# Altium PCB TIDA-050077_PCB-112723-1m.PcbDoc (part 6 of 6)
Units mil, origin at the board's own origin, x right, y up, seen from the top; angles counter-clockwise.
Board outline 3780 x 7750 mil, 16 copper layers (Top Layer, L2-Powet 1, L3-Power 2, L4-Power 3, L5-Power 4, L6-INT 1, L7-INT 2, L8-INT 3, L9-INT 4, L10-INT 5, L11-INT 6, L12-Power 5, L13-Power 6, L14-Power 7, L15-Power 8, Bottom Layer), stack 121.442 mil thick; 381 components, 136 nets, 958 pads, 3470 vias.
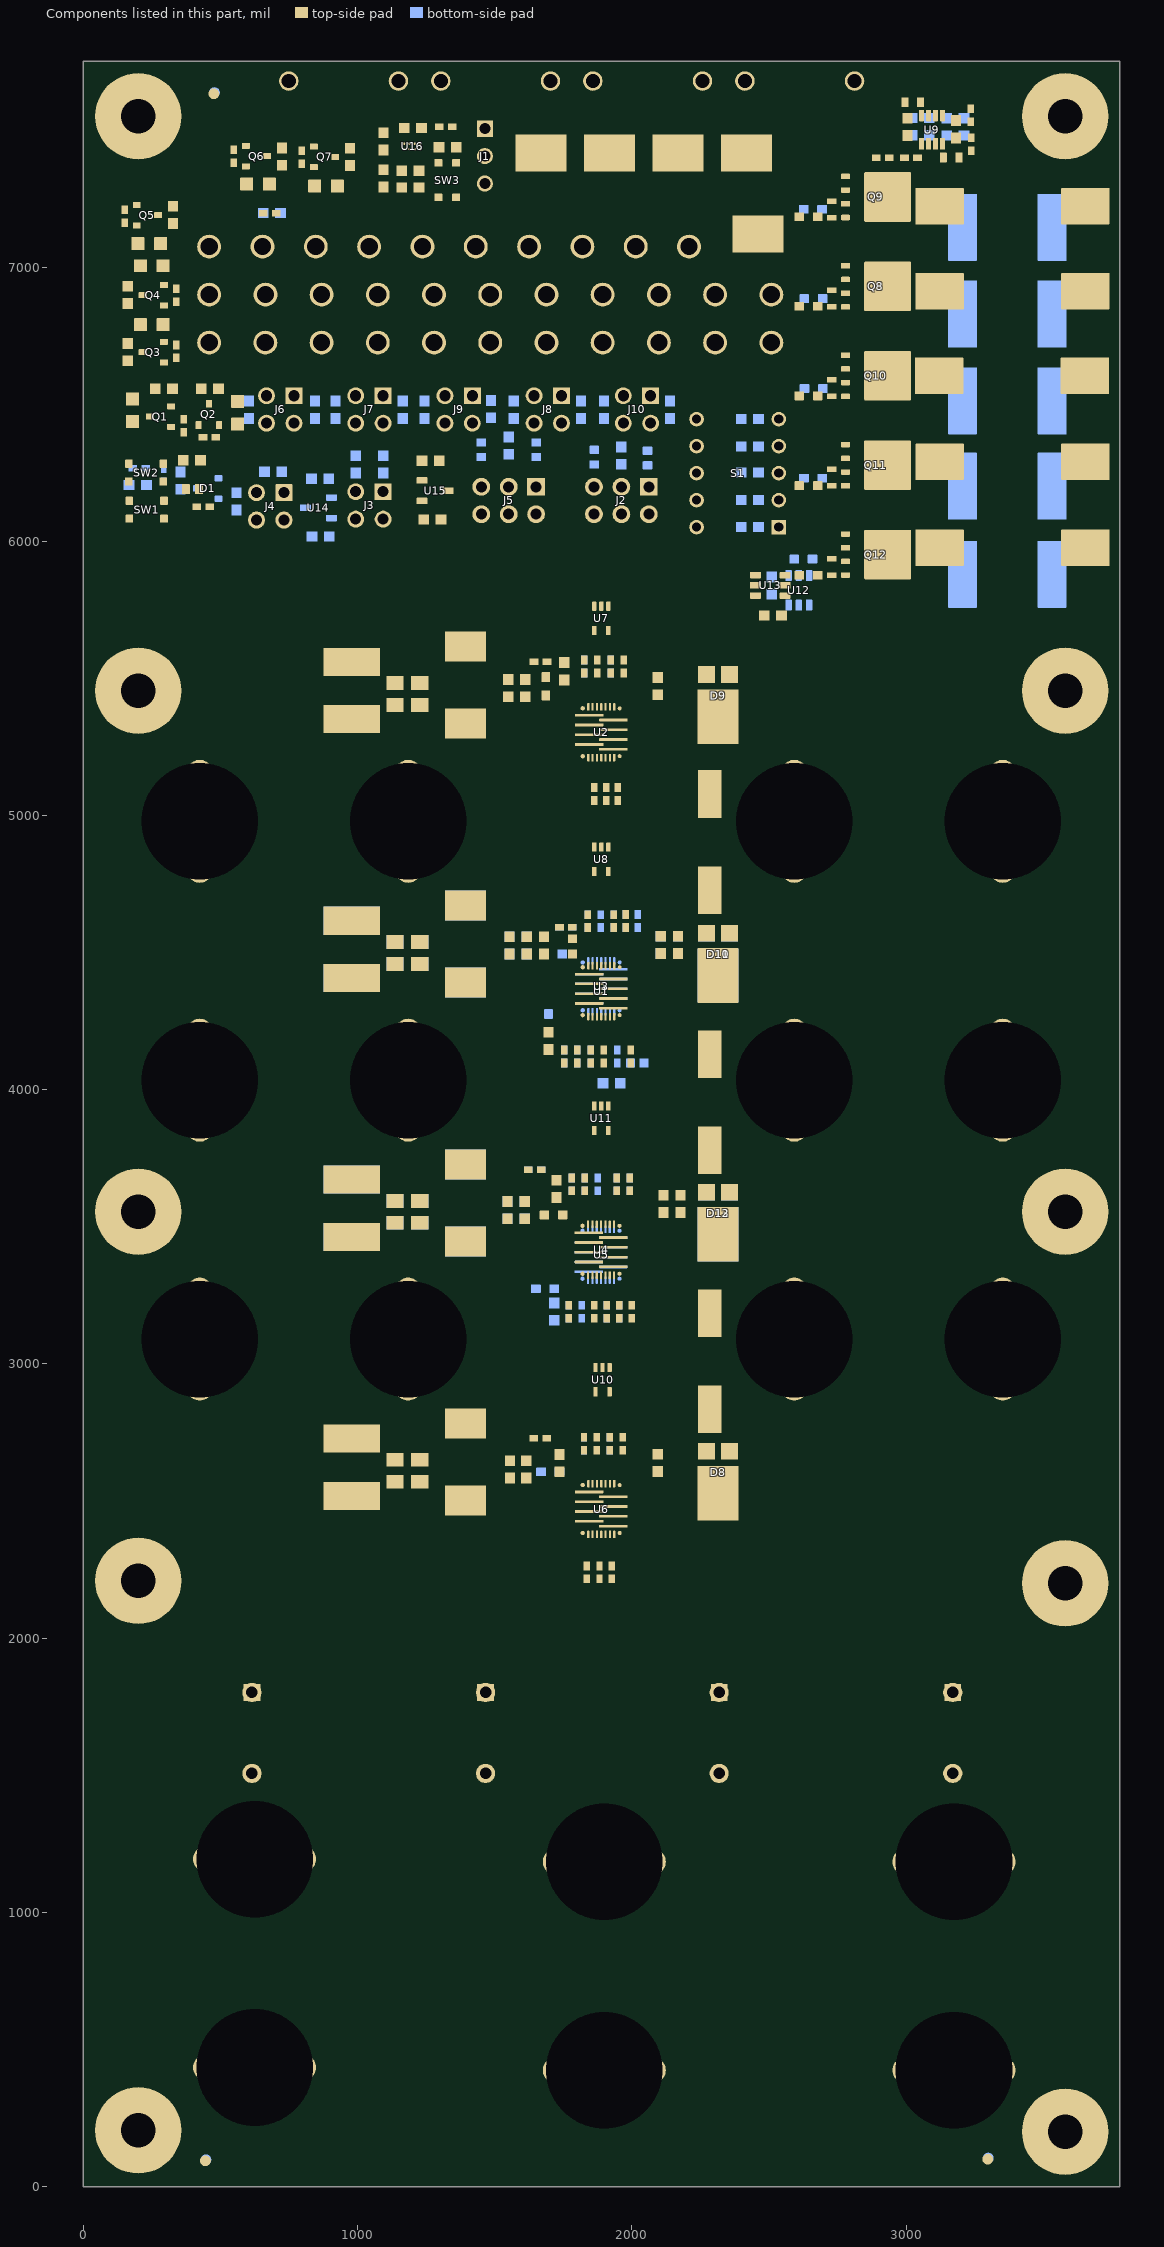
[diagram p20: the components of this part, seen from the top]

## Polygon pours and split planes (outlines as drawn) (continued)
VOUT on L15-Power 8 "L8_BOT_[PWR]_NONET_P-001" (solid, remove dead copper, pour order 1807): 3407.49,5212.29 3407.49,4755.86 3372.2,4720.57 2581.76,4720.57 2539.6,4762.73 2539.6,5216.49 2570.4,5247.29 3372.49,5247.29
VOUT on L15-Power 8 "L8_BOT_[PWR]_NONET_P-001" (solid, remove dead copper, pour order 1806): 3407.49,4268.09 3407.49,3811.67 3372.2,3776.37 2581.76,3776.37 2539.6,3818.53 2539.6,4272.29 2570.4,4303.09 3372.49,4303.09
VIN on L15-Power 8 "L8_BOT_[PWR]_NONET_P-001" (solid, remove dead copper, pour order 1682): 369.28,3804.7 369.28,4261.13 404.58,4296.42 1195.02,4296.42 1237.18,4254.26 1237.18,3800.51 1206.37,3769.7 404.28,3769.7
VIN on L15-Power 8 "L8_BOT_[PWR]_NONET_P-001" (solid, remove dead copper, pour order 1681): 369.28,4748.9 369.28,5195.87 414.03,5240.62 1195.02,5240.62 1237.18,5198.46 1237.18,4744.7 1206.37,4713.9 404.28,4713.9
QGND on L4-Power 3 "L4-POWER_3_QGND_P1609" (solid, remove dead copper, pour order 1609): 3352.36,7413.9 3386.33,7447.87 3386.33,7711.85 3373.67,7724.51 226.93,7724.51 29.23,7526.81 29.23,6081.96 82.37,6031.04 2585.13,6031.04 2654.12,6100.03 2654.12,7391.34 2676.68,7413.9
PGND on L4-Power 3 "L4-POWER_3_PGND_P1608" (solid, remove dead copper, pour order 1608): 26.96,56.7 55.66,28 3703.56,28 3746.15,70.6 3746.15,1660.54 3715.79,1690.9 48.73,1690.9 26.96,1669.12
VIN on L4-Power 3 "L4-POWER_3_VIN_P1819" (solid, remove dead copper, pour order 1819): 76.04,1723.9 1835.41,1723.9 1873.32,1761.8 1873.32,5995.34 1850.52,6018.73 73.45,6018.73 28.38,5973.66 28.38,1771.56
VOUT on L4-Power 3 "L4-POWER_3_VOUT_P1818" (solid, remove dead copper, pour order 1818): 1931.67,6018 2533.6,6018 2737.97,5813.63 3701.12,5813.63 3753.65,5761.09 3753.65,1751.37 3726.18,1723.9 1941.76,1723.9 1904.28,1761.37 1904.28,5990.62
VOUT on L4-Power 3 "L4-POWER_3_VOUT_P1603" (solid, remove dead copper, pour order 1603): 3380.94,7387.36 3721.81,7387.36 3744.28,7364.89 3744.28,5854.53 3713.49,5823.73 3391.9,5823.73 3359.28,5856.35 3359.28,7365.7
PGND on L4-Power 3 "L4-POWER_3_PGND_P1605" (solid, remove dead copper, pour order 1605): 2843.98,5931.08 2823.92,5911.02 2681.1,5911.02 2669.47,5922.65 2669.47,7376.14 2688.81,7395.49 2821.74,7395.49 2843.98,7373.25
CSA_IN- on L4-Power 3 "L4-POWER_3_CSA_IN-_P1604" (solid, remove dead copper, pour order 1604): 3332.59,5884.82 3304.22,5856.44 2882.86,5856.44 2858.8,5880.5 2858.8,7380.82 2873.03,7395.05 3312.43,7395.05 3332.59,7374.88

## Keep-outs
Keep-Out Layer:
  text ".Layer_Name" at -1006.87,-4296.96 h60

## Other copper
Top Layer:
  pour cut-out: 402.65,51.75 cw(c445.07,94.18) 402.65,136.61 cw(c445.07,94.18) 487.5,136.61 cw(c445.07,94.18) 487.5,51.75 cw(c445.07,94.18)
  pour cut-out: 3255.41,57.67 cw(c3297.84,100.1) 3255.41,142.52 cw(c3297.84,100.1) 3340.26,142.52 cw(c3297.84,100.1) 3340.26,57.67 cw(c3297.84,100.1)
  pour cut-out: 433.48,7589.49 cw(c475.9,7631.92) 433.48,7674.34 cw(c475.9,7631.92) 518.33,7674.34 cw(c475.9,7631.92) 518.33,7589.49 cw(c475.9,7631.92)
  region net VIN: 1766.64,3365.45 1786.59,3345.5 1867.13,3345.5 1869.84,3348.21 1869.84,3476.75 1864.12,3482.46 1772.57,3482.46 1766.64,3476.54
  region net VDD: 1770.34,4517.61 1765.34,4512.61 1765.34,4466.83 1794.15,4438.02 1828.21,4438.02 1829.58,4439.39 1829.58,4494.8 1806.77,4517.61
  region net VOUT: 1912.58,3347.33 2000.86,3347.33 2010.88,3357.35 2010.88,3473.97 1999.15,3485.71 1912.93,3485.71 1907.68,3480.46 1907.68,3458.33 1907.68,3352.23
  region net VOUT: 1912.58,2403.13 2000.86,2403.13 2010.88,2413.15 2010.88,2529.77 1999.15,2541.51 1912.93,2541.51 1907.68,2536.27 1907.68,2514.13 1907.68,2408.03
  region net VIN: 1766.64,2407.34 1773.87,2400.1 1865.94,2400.1 1869.84,2404 1869.84,2532.55 1864.12,2538.27 1771.32,2538.27 1766.64,2533.59
  region net VOUT: 1912.58,5235.72 2000.86,5235.72 2010.88,5245.74 2010.88,5362.36 1999.15,5374.1 1912.93,5374.1 1907.68,5368.85 1907.68,5346.72 1907.68,5240.62
  region net VIN: 1869.84,5365.14 1869.84,5235.75 1865.44,5231.34 1771.42,5231.34 1766.64,5236.12 1766.64,5366.8 1770.7,5370.86 1864.12,5370.86
  region net VOUT: 1912.58,4291.52 2000.86,4291.52 2010.88,4301.54 2010.88,4418.17 1999.15,4429.9 1912.93,4429.9 1907.68,4424.66 1907.68,4402.52 1907.68,4296.42
  region net VIN: 1793.92,4426.66 1864.12,4426.66 1869.84,4420.94 1869.84,4314.84 1864.94,4309.94 1791.44,4309.94 1787.04,4305.54 1770.74,4305.54 1766.64,4309.64 1766.64,4428.64 1771.14,4433.14 1787.44,4433.14
  text ".Layer_Name" at -1006.87,-4296.96 h60
L4-Power 3:
  text ".Layer_Name" at -1006.87,-4296.96 h60
L2-Powet 1:
  text ".Layer_Name" at -1006.87,-4296.96 h60
L8-INT 3:
  text ".Layer_Name" at -1006.87,-4296.96 h60
L3-Power 2:
  text ".Layer_Name" at -1006.87,-4296.96 h60
L7-INT 2:
  text ".Layer_Name" at -1006.87,-4296.96 h60
L5-Power 4:
  pour cut-out: 1332.85,5051.6 ccw(c1352.85,5051.6) 1352.85,5031.6 ccw(c1352.85,5051.6) 1372.85,5051.6 ccw(c1352.85,5051.6) 1352.85,5071.6 ccw(c1352.85,5051.6)
  text ".Layer_Name" at -1006.87,-4296.96 h60
L6-INT 1:
  text ".Layer_Name" at -1006.87,-4296.96 h60
L9-INT 4:
  text ".Layer_Name" at -1006.87,-4296.96 h60
L10-INT 5:
  text ".Layer_Name" at -1006.87,-4296.96 h60
L11-INT 6:
  text ".Layer_Name" at -1006.87,-4296.96 h60
L12-Power 5:
  text ".Layer_Name" at -1006.87,-4296.96 h60
L13-Power 6:
  text ".Layer_Name" at -1006.87,-4296.96 h60
L14-Power 7:
  text ".Layer_Name" at -1006.87,-4296.96 h60
L15-Power 8:
  text ".Layer_Name" at -1006.87,-4296.96 h60
Bottom Layer:
  pour cut-out: 404.75,55.83 cw(c447.18,98.26) 404.75,140.69 cw(c447.18,98.26) 489.61,140.69 cw(c447.18,98.26) 489.61,55.83 cw(c447.18,98.26)
  pour cut-out: 3257.52,61.75 cw(c3299.94,104.18) 3257.52,146.6 cw(c3299.94,104.18) 3342.37,146.6 cw(c3299.94,104.18) 3342.37,61.75 cw(c3299.94,104.18)
  pour cut-out: 435.58,7593.57 cw(c478.01,7636) 435.58,7678.42 cw(c478.01,7636) 520.43,7678.42 cw(c478.01,7636) 520.43,7593.57 cw(c478.01,7636)
  pour cut-out: 2649.62,7231.3 2668.59,7231.3 2668.59,7235.69 2649.62,7235.69
  text ".Layer_Name" at -1006.87,-4296.96 h60
Multi-Layer:
  pour cut-out: 20.22,7550 ccw(c200,7550) 200,7370.22 ccw(c200,7550) 379.78,7550 ccw(c200,7550) 200,7729.78 ccw(c200,7550)
  pour cut-out: 3400.22,7550 ccw(c3580,7550) 3580,7370.22 ccw(c3580,7550) 3759.78,7550 ccw(c3580,7550) 3580,7729.78 ccw(c3580,7550)
  pour cut-out: 3400.22,5455 ccw(c3580,5455) 3580,5275.22 ccw(c3580,5455) 3759.78,5455 ccw(c3580,5455) 3580,5634.78 ccw(c3580,5455)
  pour cut-out: 20.22,5455 ccw(c200,5455) 200,5275.22 ccw(c200,5455) 379.78,5455 ccw(c200,5455) 200,5634.78 ccw(c200,5455)
  pour cut-out: 20.22,3555 ccw(c200,3555) 200,3375.22 ccw(c200,3555) 379.78,3555 ccw(c200,3555) 200,3734.78 ccw(c200,3555)
  pour cut-out: 3400.22,3555 ccw(c3580,3555) 3580,3375.22 ccw(c3580,3555) 3759.78,3555 ccw(c3580,3555) 3580,3734.78 ccw(c3580,3555)
  pour cut-out: 3400.22,2200 ccw(c3580,2200) 3580,2020.22 ccw(c3580,2200) 3759.78,2200 ccw(c3580,2200) 3580,2379.78 ccw(c3580,2200)
  pour cut-out: 20.22,2208.9 ccw(c200,2208.9) 200,2029.12 ccw(c200,2208.9) 379.78,2208.9 ccw(c200,2208.9) 200,2388.68 ccw(c200,2208.9)
  pour cut-out: 20.22,205 ccw(c200,205) 200,25.22 ccw(c200,205) 379.78,205 ccw(c200,205) 200,384.78 ccw(c200,205)
  pour cut-out: 3400.22,200 ccw(c3580,200) 3580,20.22 ccw(c3580,200) 3759.78,200 ccw(c3580,200) 3580,379.78 ccw(c3580,200)

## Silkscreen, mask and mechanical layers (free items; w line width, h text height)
Top Overlay:
  lines w5: 24.28,6786.58 34.28,6786.58 ; 34.28,7085.12 34.28,7077.96 ; 35.1,7004.76 45.1,7004.76 ; 39.34,7083.01 34.28,7077.96 ; 41.44,7077.96 34.28,7077.96 ; 44.28,6776.58 44.28,6796.58 ; 45.1,7087.27 55.1,7087.27 ; 45.52,6806.41 52.68,6806.41 ; 46.7,7074.6 46.7,7067.44 ; 47.63,6801.35 52.68,6806.41 ; 51.75,7072.5 46.7,7067.44 ; 52.68,6799.25 52.68,6806.41 ; 53.86,7067.44 46.7,7067.44 ; 54.28,6786.58 44.28,6786.58 ; 55.1,6994.76 55.1,7014.76 ; 55.1,7077.27 55.1,7097.27 ; 56.34,7024.59 63.5,7024.59 ; 57.94,6795.89 65.1,6795.89 ; 58.44,7019.54 63.5,7024.59 ; 60.04,6790.84 65.1,6795.89 ; 63.5,7017.43 63.5,7024.59 ; 65.1,6788.73 65.1,6795.89 ; 65.1,7004.76 55.1,7004.76 ; 65.1,7087.27 75.1,7087.27 ; 68.75,7014.08 75.91,7014.08 ; 70.86,7009.02 75.91,7014.08 ; 75.91,7006.92 75.91,7014.08 ; 162.93,7260.13 170.64,7250.78 ; 208.5,6626.18 217.85,6633.9 ; 230.01,6383.27 242.52,6407.5 ; 288.63,6837.49 321.15,6827.95 ; 325.99,7123.41 333.71,7114.06 ; 330.72,6394.33 340.07,6402.04 ; 367.64,6924.31 375.43,6930.74 ; 382.59,6583.83 390.3,6574.48 ; 492.76,6347.43 500.47,6338.08 ; 514.43,6502.76 530.6,6518.92 530.6,6540.21 ; 519.78,7300.54 519.78,7293.38 ; 521.25,6953.66 530.6,6961.37 ; 521.25,7129.71 530.6,7137.43 ; 524.83,7298.44 519.78,7293.38 ; 525.68,6776.18 535.03,6783.9 ; 526.94,7293.38 519.78,7293.38 ; 530.6,7302.7 540.6,7302.7 ; 532.2,7290.03 532.2,7282.87 ; 537.25,7287.92 532.2,7282.87 ; 539.36,7282.87 532.2,7282.87 ; 540.6,7292.7 540.6,7312.7 ; 550.6,7302.7 560.6,7302.7 ; 565.18,6395.25 569.19,6390.39 ; 581.66,6582.25 601.66,6582.25 ; 591.66,6572.25 591.66,6582.25 ; 591.66,6592.25 591.66,6602.25 ; 713.82,6783.9 723.17,6791.61 ; 713.82,7126.62 723.17,7134.34 ; 718.92,6956.24 728.27,6963.96 ; 879.99,7146.2 885.67,7153.41 ; 919.61,6783.9 928.96,6791.61 ; 920.67,6956.24 930.02,6963.96 ; 938.18,7246.96 938.18,7239.8 ; 943.24,7244.85 938.18,7239.8 ; 945.34,7239.8 938.18,7239.8 ; 949,7249.12 959,7249.12 ; 950.6,7236.45 950.6,7229.29 ; 955.66,7234.34 950.6,7229.29 ; 957.76,7229.29 950.6,7229.29 ; 959,7239.12 959,7259.12 ; 969,7249.12 979,7249.12 ; 1119.37,6961.87 1128.72,6969.58 ; 1129.45,6774.07 1138.8,6781.78 ; 1132.77,7532.22 1132.77,7461.61 1141.97,7452.41 ; 1229.18,6948.53 1238.53,6956.24 ; 1268.47,7149.33 1269.87,7156.75 ; 1326.02,6146.4 1339.28,6133.9 ; 1332.52,6956.24 1341.87,6963.96 ; 1343.47,6755.19 1352.82,6762.9 ; 1383.58,3266.33 1404.68,3266.33 ; 1393.92,3276.88 1393.92,3290 ; 1394.34,3253.2 1394.34,3266.33 ; 1449.24,4264.53 1470.34,4264.53 ; 1455.82,2377.09 1476.92,2377.09 ; 1459.58,4275.08 1459.58,4288.2 ; 1459.58,5211.52 1480.69,5211.52 ; 1460,4251.4 1460,4264.53 ; 1466.17,2387.64 1466.17,2400.77 ; 1466.58,2363.97 1466.58,2377.09 ; 1469.93,5222.07 1469.93,5235.19 ; 1470.34,5198.39 1470.34,5211.52 ; 1539.7,6952.39 1549.05,6960.1 ; 1562.57,6760.23 1571.92,6767.95 ; 1749.2,6773.75 1758.55,6781.46 ; 1750.43,6945.16 1759.78,6952.88 ; 1796.75,5584.54 1796.75,5605 2001.84,5605 2001.84,5586.77 ; 1836.61,3913.94 1836.61,3925.59 ; 1836.61,4858.14 1836.61,4869.78 ; 1836.61,5736.81 1836.61,5748.45 ; 1841.37,2960.91 1841.37,2972.55 ; 1943.06,6783.25 1952.41,6790.96 ; 1949.38,6956.24 1958.73,6963.96 ; 1952.12,5615.79 1961.47,5623.5 ; 2141.48,6657.31 2146.24,6647.75 ; 2154.28,6772.35 2163.63,6780.06 ; 2154.28,6956.24 2163.63,6963.96 ; 2257.81,7134.38 2261.88,7138.16 ; 2364.28,6776.18 2373.63,6783.9 ; 2364.28,6956.24 2373.63,6963.96 ; 2836.49,7381.76 2844.21,7372.41 ; 3050.98,7368.86 3058.7,7359.51 ; 3098.65,7594.32 3106.37,7584.97 ; 3241.2,7388.71 3253.26,7387.55 ; 44.28,6786.58 34.28,6796.58 34.28,6776.58 44.28,6786.58 ; 55.1,7004.76 45.1,6994.76 45.1,7014.76 55.1,7004.76 ; 55.1,7087.27 65.1,7097.27 65.1,7077.27 55.1,7087.27 ; 540.6,7302.7 550.6,7312.7 550.6,7292.7 540.6,7302.7 ; 591.66,6582.25 601.66,6592.25 581.66,6592.25 591.66,6582.25 ; 959,7249.12 969,7259.12 969,7239.12 959,7249.12 ; 1383.58,3276.88 1394.13,3266.33 1404.68,3276.88 1383.58,3276.88 ; 1449.24,4275.08 1470.34,4275.08 1459.79,4264.53 1449.24,4275.08 ; 1455.82,2387.64 1476.92,2387.64 1466.37,2377.09 1455.82,2387.64 ; 1459.58,5222.07 1480.69,5222.07 1470.14,5211.52 1459.58,5222.07 ; 1968.85,5615.96 2150.42,5615.96 2150.42,5758.43 1968.85,5758.43 1968.85,5615.96
  text "QGND" at 2117.98,7521.02 h30
  text "QGND" at 2365.42,7517.35 h30
  text "QGND" at 1620.42,7515.45 h30
  text "QGND" at 1869.25,7515.45 h30
  text "QGND" at 2338.72,7057.42 h30 r90
  text "EN" at 567.72,7055.04 h30 r90
  text "FLTb3" at 1152.46,7029.18 h30 r90
  text "IREF" at 762.16,7027.55 h30 r90
  text "TEMP" at 1928.83,7025.05 h30 r90
  text "MODE" at 2123.27,7025.05 h30 r90
  text "ILIM1" at 1345.49,7020.05 h30 r90
  text "ILIM2" at 1539.94,7015.05 h30 r90
  text "FLTb2" at 956.6,7010.05 h30 r90
  text "PG" at 2620.04,6893.91 h30 r90
  text "VIN" at 567.72,6867.54 h30 r90
  text "+5V" at 977.72,6865.04 h30 r90
  text "PGND" at 773.21,6850.05 h30 r90
  text "VOUT" at 2412.72,6850.05 h30 r90
  text "ILIM5" at 2208.08,6830.05 h30 r90
  text "+3P3V" at 1187.5,6825.14 h30 r90
  text "FLTb4" at 1387.72,6816.77 h30 r90
  text "FLTb5" at 1602.5,6815.8 h30 r90
  text "FLTb" at 987.06,6666.27 h30 r90
  text "IMON" at 1185.82,6665.84 h30 r90
  text "ILIM" at 1389.27,6658.03 h30 r90
  text "ITIMER" at 776.68,6628.04 h30 r90
  text "FLTb_1" at 570.89,6620.8 h30 r90
  text "ILIM4" at 1828.75,6609.09 h30
  text "ILIM_3" at 2097.59,6609.13 h30
  text "DVDT" at 2295.43,6609.09 h30
  text "SWEN" at 2459.01,6609.09 h30
  text "ILIM1" at 652.44,6339.76 h30
  text "ILIM4" at 1316.41,6339.97 h30
  text "ILIM3" at 1623.11,6339.76 h30
  text "ILIM5" at 1948.34,6339.76 h30
  text "ILIM2" at 984.11,6337.74 h30
  text "ITIMER" at 1459.26,6009.07 h30
  text "DVDT" at 1898.01,6004.8 h30
  text "IMON" at 985.16,5989.76 h30
  text "ILIM" at 625.87,5986.32 h30
  text "ON" at 2189.28,5912.4 h30
  text "OFF" at 2495.97,5912.4 h30
  text "Contact may cause burns." at 134.71,5838.8 h110
  text "Do not touch!" at 416.91,5752.1 h110
  text "300A Maximum DC" at 310.01,5665.3 h60
  text "Contact may cause burns." at 2270,5630 h110
  text "Do not touch!" at 2598.84,5542.1 h110
  text "300A Maximum DC" at 2491.94,5455.3 h60
  text "VIN" at 279.74,4922.67 h45 r90
  text "VOUT" at 3576.69,4917.19 h45 r90
  text "VOUT" at 3556.69,3982.19 h45 r90
  text "VIN" at 268.71,3977.93 h45 r90
  text "VIN" at 293.71,3087.93 h45 r90
  text "VOUT" at 3553.63,3032.19 h45 r90
  text "TIDA-050077" at 2623.43,2427.86 h75
  text "REV A" at 2889.47,2332.8 h45
  text "PGND" at 539.26,228.31 h45
  text "PGND" at 1814.26,223.31 h45
  text "PGND" at 3104.09,213.31 h45
  text "For evaluation only; not FCC approved for resale." at 1965,46.32 h60
  text ".Layer_Name" at -1006.87,-4296.96 h60
Bottom Overlay:
  drawing of 2368 lines, arcs and shapes, not listed
  text "305-PD-23-1137" at 3202.57,2127.45 h40
  text "NOV 2023" at 3191.51,2057.9 h40
  text ".Layer_Name" at -1086.87,-4291.96 h50
Top Paste:
  text ".Layer_Name" at -1006.87,-4296.96 h60
Bottom Paste:
  text ".Layer_Name" at -1006.87,-4296.96 h60
Top Solder:
  text ".Layer_Name" at -1006.87,-4296.96 h60
  text ".Layer_Name" at -1006.87,-4296.96 h60
Bottom Solder:
  text ".Layer_Name" at -1006.87,-4296.96 h60
Drill Guide:
  text ".Layer_Name" at -1006.87,-4296.96 h60
M1 Board Outline:
  lines w10: -1875.72,8528.04 -1875.37,8528.04 ; 0,0 0,7750 3780,7750 3780,0 0,0
  text ".Layer_Name" at -1006.87,-4296.96 h60
M2 Board Dimensions:
  rectangle: 41.13,-2731.1 416.13,-2606.1
  rectangle: -83.87,-2606.1 41.13,-2481.1
  lines w7: -83.87,-2606.1 916.13,-2606.1 ; 41.13,-2731.1 41.13,-2481.1 ; 166.13,-2731.1 166.13,-2481.1 ; 416.13,-2731.1 416.13,-2481.1 ; 666.13,-2731.1 666.13,-2481.1 ; -83.87,-2731.1 -83.87,-2481.1 916.13,-2481.1 916.13,-2731.1 -83.87,-2731.1
  text ".Layer_Name" at -1006.87,-4296.96 h60
M3 3D STEP Top:
  text ".Layer_Name" at -1006.87,-4296.96 h60
M4 3D STEP Bottom:
  text ".Layer_Name" at -1006.87,-4296.96 h60
M5 Assembly Top:
  lines w10: -1875.87,-4368.63 4724.13,-4368.63 ; -1875.87,-4165.3 4726.13,-4165.3 ; -1875.87,-3961.96 -1875.87,-4571.96 2129.13,-4571.96 4726.13,-4571.96 4726.13,-3961.96 -1875.37,-3961.96 -1875.37,-4571.96 -299.87,-4571.96 ; 589.13,-4571.96 589.13,-3961.96 ; 1856.13,-4165.3 1856.13,-3961.96 ; 2696.13,-4165.3 2696.13,-3961.96 ; 3318.13,-4578.46 3318.13,-4375.63
  text "COMPONENTS MARKED 'DNP' SHOULD NOT BE POPULATED." at -430.37,-3756.96 h60
  text "ASSEMBLY VARIANT:" at -430.87,-3872.46 h60
  text ".VariantName" at 605.13,-3872.46 h60
  text "PCB VIEWED FROM TOP SIDE" at -1812.37,-4094.13 h60
  text "BOARD #:" at 664.13,-4094.13 h60
  text ".PRJ_Number" at 1209.63,-4094.13 h60
  text "REV:" at 2054.13,-4094.13 h60
  text ".PCB_Rev" at 2345.63,-4094.13 h60
  text "SVN REV:" at 2892.13,-4094.13 h60
  text ".VersionControl_RevNumber" at 3398.13,-4094.13 h60
  text "TID #:" at 664.13,-4297.46 h60
  text ".TID" at 1209.63,-4297.46 h60
  text "PLOT NAME =" at -1812.37,-4502.8 h60
  text ".plot_File_Name" at -1006.87,-4502.8 h60
  text "GENERATED    :" at 666.13,-4502.8 h60
  text ".Print_Date" at 1535.63,-4502.8 h60
  text ".Print_Time" at 2264.63,-4502.8 h60
  text "TEXAS INSTRUMENTS" at 3529.13,-4502.8 h60
M6 Assembly Bottom:
  lines w10: -1876.37,-4165.8 4725.63,-4165.8 ; -1874.37,-4369.13 4725.63,-4369.13 ; -468.37,-4578.96 -468.37,-4376.13 ; 153.63,-4165.8 153.63,-3962.46 ; 993.63,-4165.8 993.63,-3962.46 ; 2260.63,-4572.46 2260.63,-3962.46 ; 3149.63,-4572.46 4725.13,-4572.46 4725.13,-3962.46 -1876.37,-3962.46 -1876.37,-4572.46 720.63,-4572.46 4725.63,-4572.46 4725.63,-3962.46
  text "COMPONENTS MARKED 'DNP' SHOULD NOT BE POPULATED." at 4518.13,-3756.46 h60
  text ".VariantName" at 3474.13,-3872.46 h60
  text "ASSEMBLY VARIANT:" at 4513.13,-3872.46 h60
  text ".VersionControl_RevNumber" at -548.37,-4094.63 h60
  text "SVN REV:" at -42.37,-4094.63 h60
  text ".PCB_Rev" at 504.13,-4094.63 h60
  text "REV:" at 795.63,-4094.63 h60
  text ".PRJ_Number" at 1640.13,-4094.63 h60
  text "BOARD #:" at 2185.63,-4094.63 h60
  text "PCB VIEWED FROM BOTTOM SIDE" at 4662.13,-4094.63 h60
  text ".TID" at 1640.13,-4297.96 h60
  text "TID #:" at 2185.63,-4297.96 h60
  text "TEXAS INSTRUMENTS" at -679.37,-4503.3 h60
  text ".Print_Time" at 585.13,-4503.3 h60
  text ".Print_Date" at 1314.13,-4503.3 h60
  text "GENERATED    :" at 2183.63,-4503.3 h60
  text ".plot_File_Name" at 3856.63,-4503.3 h60
  text "PLOT NAME =" at 4662.13,-4503.3 h60
M9 Title Sheet:
  drawing of 64 lines, arcs and shapes, not listed
  text "1" at -725.72,8598.9 h70
  text "2" at 1774.28,8598.9 h70
  text "3" at 4140.98,8598.04 h70
  text "4" at 6647.64,8598.04 h70
  text "5" at 9146.63,8598.04 h70
  text "6" at 14151.63,8598.04 h70
  text "A" at -2000.37,3455.04 h70
  text "A" at 15299.63,3455.04 h70
  text "B" at -2000.37,1075.04 h70
  text "B" at 15299.63,1075.04 h70
  text "C" at -2000.37,-1299.96 h70
  text "C" at 15299.63,-1299.96 h70
  text "PROJECT TITLE:" at 12259.63,-3160.96 h45
  text ".PRJ_Title" at 12309.63,-3294.29 h70
  text "DESIGNED FOR:" at 12259.63,-3461.96 h45
  text ".PRJ_Customer" at 12309.63,-3601.96 h70
  text "D" at -2000.37,-3669.96 h70
  text "D" at 15299.63,-3669.96 h70
  text "FILE NAME:" at 12259.63,-3761.96 h45
  text "PSIL196A_TPS25984EVM" at 12309.63,-3881.96 h70
  text "Texas Instruments (TI) and/or its licensors do not warrant the accuracy or completeness of this specification" at 7290.13,-4043.8 h45
  text "ENGINEER:" at 12259.63,-4051.96 h45
  text "LAYOUT BY:" at 13764.63,-4051.96 h45
  text "or any information contained therein. TI and/or its licensors do not warrant that this design will meet" at 7245.15,-4156.47 h45
  text ".PRJ_Engineer" at 12303.09,-4163.38 h70
  text "Pactron" at 13808.59,-4163.38 h70
  text "Avishek Pal" at 12283.59,-4183.38 h70
  text "the specifications, will be suitable for your application or fit for any particular purpose, or will operate in" at 7245.15,-4269.13 h45
  text ".Layer_Name" at -1006.87,-4296.96 h60
  text "ALTIUM DESIGNER VERSION:" at 13764.63,-4361.96 h45
  text "an implementation. TI and/or its licensors do not warrant that the design is production worthy. You should" at 7245.15,-4381.8 h45
  text "completely validate and test your design implementation to confirm the system functionality for your application." at 7290.13,-4494.46 h45
  text ".print_Scale" at 12309.63,-4495.29 h70
  text ".Application_BuildNumber" at 13815.13,-4495.29 h70
  text "1" at -844.03,-4701.96 h70
  text "2" at 1651.63,-4701.96 h70
  text "3" at 4140.98,-4701.96 h70
  text "4" at 6647.64,-4701.96 h70
  text "5" at 9146.63,-4701.96 h70
  text "6" at 14151.63,-4701.96 h70
M10 Fab Notes:
  drawing of 189 lines, arcs and shapes, not listed
  text "DESIGN INFORMATION" at 13298.15,2917.71 h60
  text "MIN. TRACK WIDTH:" at 12653.59,2785.58 h60
  text "6" at 13749.83,2785.59 h60
  text "MIL" at 13904.59,2785.58 h60
  text "6" at 13744.83,2664.94 h60
  text "MIN. CLEARANCE:" at 12653.59,2661.46 h60
  text "MIL" at 13904.59,2661.46 h60
  text "MIN. VIA PAD SIZE:" at 12653.59,2537.33 h60
  text "16" at 13719.84,2537.33 h60
  text "MIL" at 13904.59,2537.33 h60
  text "0.05mm (2MIL)" at 13348.59,2407.43 h60
  text "MINIMUM ANNULAR RING" at 12324.36,2399.21 h60
  text "EXTERNAL" at 14056.59,2399.21 h60
  text "PER" at 12524.36,2289.08 h60
  text "IPC-D-275 CLASS 2 LEVEL C" at 12744.36,2289.08 h60
  text "MIL, HOLES" at 14232.59,2188.6 h60
  text "+/-" at 13840.13,2180.02 h60
  text "+/-" at 14694.13,2180.02 h60
  text "REGISTRATION TOLERANCES:" at 12324.36,2178.95 h60
  text "METAL" at 13524.13,2178.95 h60
  text "5" at 14100.33,2178.96 h60
  text "3" at 14933.33,2178.96 h60
  text "MIL" at 15049.59,2178.95 h60
  text "HOLE SIZE TOLERANCE (UNLESS OTHERWISE SPECIFIED):" at 12324.36,2080.64 h60
  text "+/-" at 14694.13,2077.77 h60
  text "3" at 14933.33,2076.71 h60
  text "MIL" at 15049.59,2076.7 h60
  text "MATERIAL:" at 12249.59,1939.06 h60
  text "FR-4 High Tg" at 13236.03,1810.53 h60
  text "X" at 13091.6,1802.54 h60
  text "FR-408" at 12670.59,1798.02 h60
  text "OTHER" at 14158.59,1798.02 h60
  text "62 MIL (1.6mm) +/-10%" at 12990.69,1654.99 h60
  text "118MIL =/-11.811MIL" at 14575.69,1654.99 h40
  text "X" at 14157.6,1652.54 h60
  text "THICKNESS:" at 12324.36,1646.77 h60
  text "OTHER" at 14275.59,1646.77 h60
  text "TOLERANCE:" at 12324.36,1508.46 h60
  text "X" at 13172.6,1508.46 h60
  text "ANSI IPC-6012 TYPE 3 CLASS 2" at 13350.61,1508.46 h60
  text "OTHER +/-" at 13350.59,1364.27 h60
  text "BOW & TWIST:" at 12324.36,1219.08 h60
  text "X" at 13172.6,1219.08 h60
  text "ANSI IPC-6012 TYPE 3 CLASS 2" at 13350.61,1219.08 h60
  text "OTHER +/-" at 13350.59,1072.38 h60
  text "DRILLING:" at 12249.59,941.77 h60
  text "NC_DRILL FILES" at 14010.59,836.58 h60
  text "REFERENCE:" at 12324.36,832.64 h60
  text "X" at 12981.6,832.54 h60
  text "AS SHOWN" at 13159.59,832.64 h60
  text "X" at 13882.6,832.64 h60
  text "OTHER" at 14308.59,690.39 h60
  text "PTH COPPER THICKNESS:" at 12324.04,686.86 h60
  text "X" at 13463.27,686.86 h60
  text "20-30 um" at 13591.27,686.86 h60
  text "BOARD FINISH:" at 12249.59,539.26 h60
  text "SILKSCREEN:" at 12404.81,429.14 h60
  text "X" at 13362.6,429.14 h60
  text "TOP" at 13479.59,429.14 h60
  text "X" at 13872.6,429.14 h60
  text "BOTTOM" at 13990.59,429.14 h60
  text "SILKSCREEN COLOR:" at 12404.81,273.95 h60
  text "X" at 13361.6,273.95 h60
  text "WHITE" at 13479.59,273.95 h60
  text "OTHER" at 13990.59,273.95 h60
  text "X" at 13492.6,130.5 h60
  text "GREEN" at 13610.59,130.5 h60
  text "OTHER" at 14228.59,130.5 h60
  text "SOLDER RESIST COLOR:" at 12404.81,123.63 h60
  text "X" at 13492.6,-23.75 h60
  text "MATTE" at 13610.59,-23.75 h60
  text "SEMI-GLOSS" at 14228.13,-24.39 h60
  text "IMMERSION GOLD (ENIG)" at 13310.59,-196.53 h60
  text "ENEPIG" at 14648.13,-203.75 h60
  text "SURFACE FINISH:" at 12249.59,-204.75 h60
  text "X" at 13132.6,-204.75 h60
  text "IMM. TIN/SILVER OR EQUIV" at 12579.13,-342.06 h60
  text "OTHER" at 14010.59,-346 h60
  text "ARRAY/PANEL:" at 12249.59,-501.38 h60
  text "X" at 13132.6,-505.57 h60
  text "CUT AND TRIM PER M1 BOARD OUTLINE" at 13310.59,-509.6 h60
  text "N.C. ROUTE" at 13310.59,-645.57 h60
  text "V. SCORE" at 14176.59,-645.57 h60
  text "CERTIFICATION:" at 12249.59,-774.69 h60
  text "MATERIALS AND WORKMANSHIP FOR ALL PCBS" at 12974.59,-774.69 h60
  text "FAB NOTE:" at 4564.53,-823.67 h100
  text "TO MEET OR EXCEED THE REQUIREMENTS OF:" at 12974.59,-868.75 h60
  text "X" at 12612.1,-997.38 h60
  text "ANSI IPC-A-600F CLASS ->" at 12740.09,-997.38 h60
  text "X" at 14388.1,-997.38 h60
  text "2" at 14498.09,-997.38 h60
  text "1" at 14183.1,-998.88 h60
  text "3" at 14852.09,-998.88 h60
  text "1.10MIL,12MIL AND 12.1MIL DRILLS SHOULD BE NON-CONDUCTIVE VIA FILLED AND PLATTED OVER ON" at 4786.62,-1110.3 h80
  text "X" at 13424.1,-1145.07 h60
  text "RoHS" at 13552.1,-1145.07 h60
  text "OTHER" at 14196.5,-1145.07 h60
  text "PER ORDER" at 14593.55,-1145.07 h60
  text "BOTH SIDES TO HAVE SURFACE FLAT AND SMOOTH IN SUCH A MANNER THERE IS NO DISCONTINUITY." at 5004.23,-1276.48 h80
  text "ALL BOARDS MUST MEET OR EXCEED UL94-V0 REQUIREMENTS." at 12277.13,-1298.9 h60
  text "PCB MUST BEAR THE UL94V-0 UL REGISTERED MATERIAL ID NUMBER" at 12277.13,-1414.96 h60
  text "2.10MIL AND 12MILL DRILLS SHOULD BE NON-CONDUCTIVE VIA PLUG FROM BOTTOM SIDE" at 4786.62,-1469.31 h80
  text "ADDITIONAL REQUIREMENTS:" at 12249.59,-1584.38 h60
  text "3. NO VENDOR LOGO OR NAME ON THE BOARD" at 4786.62,-1635.48 h80
  text "MICROSECTION:" at 12324.36,-1691.51 h60
  text "YES" at 13230.09,-1691.51 h60
  text "4. CLIP SILKSCREEN ON NO MASK AREA." at 4786.62,-1801.66 h80
  text "REQUIRED" at 14091.59,-1835.84 h60
  text "BARE BOARD ELEC. TEST:" at 12324.36,-1838.7 h60
  text "NONE" at 13630.09,-1838.7 h60
  text "X" at 13973.6,-1838.7 h60
  text "PER ORDER" at 14683.59,-1838.7 h60
  text "5. ALL DRILL SIZE'S ARE FINISHED HOLE SIZE" at 4786.62,-1981.16 h80
  text "XX MIL VIAS REQUIRE NON-CONDUCTIVE FILL AND PLANARIZE" at 12492.51,-2043.65 h59
  text "6. NEED TO REMOVE THE NON FUNCTIONAL PADS IN INNER LAYERS" at 4784.14,-2147.34 h80
  text "XX MIL VIAS REQUIRE CONDUCTIVE FILL AND PLANARIZE" at 12500.51,-2147.62 h60
  text "OUTER XX MIL TRACES REQUIRE 50 OHM SINGLE-ENDED IMPEDANCE" at 12499.52,-2311.01 h58
  text "7. FOLLOW BIG SIZE 42MIL DRILL FOR REDUNDANT DRILL." at 4784.14,-2313.51 h80
  text "LAYER 2 & 3 (INNER LAYERS) XX MIL WIDE, XX MIL SPACE / TRACES REQUIRE 100 OHM DIFFERENTIAL IMPEDANCE" at 12491.52,-2546.72 h60
  text ".Layer_Name" at -1006.87,-4296.96 h60
M11 Gerber Information:
  circle w10: c4010.83,-147.55 r122.92
  circle w10: c4010.83,-147.55 r64.54
  circle w10: c4010.83,7952.45 r122.92
  circle w10: c4010.83,7952.45 r64.54
  circle w10: c-389.17,7952.45 r122.92
  circle w10: c-389.17,7952.45 r64.54
  lines w10: -1875.87,-4368.63 4724.13,-4368.63 ; -1875.87,-4165.3 4726.13,-4165.3 ; -1875.87,-3961.96 -1875.87,-4571.96 2129.13,-4571.96 4726.13,-4571.96 4726.13,-3961.96 -1875.37,-3961.96 -1875.37,-4571.96 -299.87,-4571.96 ; -554.42,7951.97 -388.69,7951.97 ; -389.16,7786.72 -389.16,7952.45 ; -389.16,8117.71 -389.16,7951.98 -223.43,7951.97 ; 589.13,-4434.54 589.13,-3961.96 ; 1856.13,-4165.3 1856.13,-3961.96 ; 2696.13,-4165.3 2696.13,-3961.96 ; 3318.13,-4578.46 3318.13,-4375.63 ; 3845.58,-148.03 4011.31,-148.03 ; 3845.58,7951.97 4011.31,7951.97 ; 4010.84,-313.28 4010.84,-147.55 ; 4010.84,17.71 4010.84,-148.02 4176.57,-148.03 ; 4010.84,7786.72 4010.84,7952.45 ; 4010.84,8117.71 4010.84,7951.98 4176.57,7951.97
  text "ALL ARTWORK VIEWED FROM TOP SIDE" at -1812.37,-4094.13 h60
  text "BOARD #:" at 664.13,-4094.13 h60
  text ".PRJ_Number" at 1209.63,-4094.13 h60
  text "REV:" at 1904.13,-4094.13 h60
  text ".PCB_Rev" at 2195.63,-4094.13 h60
  text "SVN REV:" at 2892.13,-4094.13 h60
  text ".VersionControl_RevNumber" at 3398.13,-4094.13 h60
  text "LAYER NAME =" at -1812.37,-4296.96 h60
  text "TID #:" at 664.13,-4297.46 h60
  text ".TID" at 1209.63,-4297.46 h60
  text "GENERATED    :" at 639.73,-4453.77 h60
  text ".Print_Date" at 1509.23,-4453.77 h60
  text ".Print_Time" at 2238.23,-4453.77 h60
  text "PLOT NAME =" at -1812.37,-4502.8 h60
  text "TEXAS INSTRUMENTS" at 3529.13,-4502.8 h60
  text ".plot_File_Name" at -1150.08,-4537.04 h60
M12 Stackup:
  drawing of 967 lines, arcs and shapes, not listed
  text "STACK UP:" at 5204.97,4073.9 h80
  text "Layer" at 5274.97,3928.9 h60
  text "Name" at 5684.88,3928.9 h60
  text "Material" at 6614.63,3928.9 h60
  text "Thickness" at 7474.39,3928.9 h60
  text "Constant" at 8124.23,3928.9 h60
  text "Board Layer Stack" at 8694.09,3928.9 h60
  text "Top Overlay" at 5684.88,3808.9 h60
  text "Top Solder" at 5684.88,3688.9 h60
  text "Solder Resist" at 6614.63,3688.9 h60
  text "1.00mil" at 7474.39,3688.9 h60
  text "3.5" at 8124.23,3688.9 h60
  text "1" at 5274.97,3568.9 h60
  text "Top Layer" at 5684.88,3568.9 h60
  text "Copper" at 6614.63,3568.9 h60
  text "2.80mil" at 7474.39,3568.9 h60
  text "2 Oz (0.5 + Plating)" at 9936.14,3567.49 h60
  text "Dielectric 1" at 5684.88,3448.9 h60
  text "FR-4 High TG" at 6614.63,3448.9 h60
  text "5.49mil" at 7474.39,3448.9 h60
  text "4.2" at 8124.23,3448.9 h60
  text "2" at 5274.97,3328.9 h60
  text "L2-Powet 1" at 5684.88,3328.9 h60
  text "Copper" at 6614.63,3328.9 h60
  text "2.80mil" at 7474.39,3328.9 h60
  text "2 Oz" at 9936.14,3327.48 h60
  text "Dielectric 2" at 5684.88,3208.9 h60
  text "FR-4 High TG" at 6614.63,3208.9 h60
  text "5.12mil" at 7474.39,3208.9 h60
  text "4.2" at 8124.23,3208.9 h60
  text "3" at 5274.97,3088.9 h60
  text "L3-Power 2" at 5684.88,3088.9 h60
  text "Copper" at 6614.63,3088.9 h60
  text "2.80mil" at 7474.39,3088.9 h60
  text "2 Oz" at 9936.14,3087.48 h60
  text "Dielectric 3" at 5684.88,2968.9 h60
  text "FR-4 High TG" at 6614.63,2968.9 h60
  text "4.97mil" at 7474.39,2968.9 h60
  text "4.2" at 8124.23,2968.9 h60
  text "4" at 5274.97,2848.9 h60
  text "L4-Power 3" at 5684.88,2848.9 h60
  text "Copper" at 6614.63,2848.9 h60
  text "2.80mil" at 7474.39,2848.9 h60
  text "2 Oz" at 9936.14,2847.48 h60
  text "Dielectric 4" at 5684.88,2728.9 h60
  text "FR-4 High TG" at 6614.63,2728.9 h60
  text "5.12mil" at 7474.39,2728.9 h60
  text "4.2" at 8124.23,2728.9 h60
  text "5" at 5274.97,2608.9 h60
  text "L5-Power 4" at 5684.88,2608.9 h60
  text "Copper" at 6614.63,2608.9 h60
  text "2.80mil" at 7474.39,2608.9 h60
  text "2 Oz" at 9936.14,2607.48 h60
  text "Dielectric 5" at 5684.88,2488.9 h60
  text "FR-4 High TG" at 6614.63,2488.9 h60
  text "4.97mil" at 7474.39,2488.9 h60
  text "4.2" at 8124.23,2488.9 h60
  text "6" at 5274.97,2368.9 h60
  text "L6-INT 1" at 5684.88,2368.9 h60
  text "Copper" at 6614.63,2368.9 h60
  text "2.80mil" at 7474.39,2368.9 h60
  text "2 Oz" at 9936.14,2367.48 h60
  text "Dielectric 6" at 5684.88,2248.9 h60
  text "FR-4 High TG" at 6614.63,2248.9 h60
  text "5.12mil" at 7474.39,2248.9 h60
  text "4.2" at 8124.23,2248.9 h60
  text "7" at 5274.97,2128.9 h60
  text "L7-INT 2" at 5684.88,2128.9 h60
  text "Copper" at 6614.63,2128.9 h60
  text "2.80mil" at 7474.39,2128.9 h60
  text "2 Oz" at 9936.81,2125.3 h60
  text "Dielectric 7" at 5684.88,2008.9 h60
  text "FR-4 High TG" at 6614.63,2008.9 h60
  text "4.97mil" at 7474.39,2008.9 h60
  text "4.2" at 8124.23,2008.9 h60
  text "8" at 5274.97,1888.9 h60
  text "L8-INT 3" at 5684.88,1888.9 h60
  text "Copper" at 6614.63,1888.9 h60
  text "2.80mil" at 7474.39,1888.9 h60
  text "2 Oz" at 9936.81,1887.48 h60
  text "Dielectric 8" at 5684.88,1768.9 h60
  text "FR-4 High TG" at 6614.63,1768.9 h60
  text "5.12mil" at 7474.39,1768.9 h60
  text "4.2" at 8124.23,1768.9 h60
  text "9" at 5274.97,1648.9 h60
  text "L9-INT 4" at 5684.88,1648.9 h60
  text "Copper" at 6614.63,1648.9 h60
  text "2.80mil" at 7474.39,1648.9 h60
  text "2 Oz" at 9936.81,1647.48 h60
  text "Dielectric 9" at 5684.88,1528.9 h60
  text "FR-4 High TG" at 6614.63,1528.9 h60
  text "4.97mil" at 7474.39,1528.9 h60
  text "4.2" at 8124.23,1528.9 h60
  text "10" at 5274.97,1408.9 h60
  text "L10-INT 5" at 5684.88,1408.9 h60
  text "Copper" at 6614.63,1408.9 h60
  text "2.80mil" at 7474.39,1408.9 h60
  text "2 Oz" at 9936.81,1407.48 h60
  text "Dielectric 10" at 5684.88,1288.9 h60
  text "FR-4 High TG" at 6614.63,1288.9 h60
  text "5.12mil" at 7474.39,1288.9 h60
  text "4.2" at 8124.23,1288.9 h60
  text "11" at 5274.97,1168.9 h60
  text "L11-INT 6" at 5684.88,1168.9 h60
  text "Copper" at 6614.63,1168.9 h60
  text "2.80mil" at 7474.39,1168.9 h60
  text "2 Oz" at 9936.81,1167.48 h60
  text "Dielectric 11" at 5684.88,1048.9 h60
  text "FR-4 High TG" at 6614.63,1048.9 h60
  text "4.97mil" at 7474.39,1048.9 h60
  text "4.2" at 8124.23,1048.9 h60
  text "12" at 5274.97,928.9 h60
  text "L12-Power 5" at 5684.88,928.9 h60
  text "Copper" at 6614.63,928.9 h60
  text "2.80mil" at 7474.39,928.9 h60
  text "2 Oz" at 9936.81,927.48 h60
  text "Dielectric 12" at 5684.88,808.9 h60
  text "FR-4 High TG" at 6614.63,808.9 h60
  text "5.12mil" at 7474.39,808.9 h60
  text "4.2" at 8124.23,808.9 h60
  text "13" at 5274.97,688.9 h60
  text "L13-Power 6" at 5684.88,688.9 h60
  text "Copper" at 6614.63,688.9 h60
  text "2.80mil" at 7474.39,688.9 h60
  text "2 Oz" at 9937.48,685.3 h60
  text "Dielectric 13" at 5684.88,568.9 h60
  text "FR-4 High TG" at 6614.63,568.9 h60
  text "4.97mil" at 7474.39,568.9 h60
  text "4.2" at 8124.23,568.9 h60
  text "2 Oz" at 9943.83,457.48 h60
  text "14" at 5274.97,448.9 h60
  text "L14-Power 7" at 5684.88,448.9 h60
  text "Copper" at 6614.63,448.9 h60
  text "2.80mil" at 7474.39,448.9 h60
  text "Dielectric 14" at 5684.88,328.9 h60
  text "FR-4 High TG" at 6614.63,328.9 h60
  text "5.12mil" at 7474.39,328.9 h60
  text "4.2" at 8124.23,328.9 h60
  text "2 Oz" at 9943.83,217.48 h60
  text "15" at 5274.97,208.9 h60
  text "L15-Power 8" at 5684.88,208.9 h60
  text "Copper" at 6614.63,208.9 h60
  text "2.80mil" at 7474.39,208.9 h60
  text "Dielectric 15" at 5684.88,88.9 h60
  text "FR-4 High TG" at 6614.63,88.9 h60
  text "5.49mil" at 7474.39,88.9 h60
  text "4.2" at 8124.23,88.9 h60
  text "2 Oz (0.5+ Plating)" at 9938.83,-28.34 h60
  text "16" at 5274.97,-31.1 h60
  text "Bottom Layer" at 5684.88,-31.1 h60
  text "Copper" at 6614.63,-31.1 h60
  text "2.80mil" at 7474.39,-31.1 h60
  text "Bottom Solder" at 5684.88,-151.1 h60
  text "Solder Resist" at 6614.63,-151.1 h60
  text "1.00mil" at 7474.39,-151.1 h60
  text "3.5" at 8124.23,-151.1 h60
  text "Bottom Overlay" at 5684.88,-271.1 h60
  text "Total board thickness:" at 5274.97,-391.1 h60
  text "123.44mil" at 7474.39,-391.1 h60
  text ".Layer_Name" at -1006.87,-4296.96 h60
M13 Component Bodies Top:
  text ".Layer_Name" at -1006.87,-4296.96 h60
M14 Component Bodies Bottom:
  text ".Layer_Name" at -1006.87,-4296.96 h60
M15 Courtyards Top:
  text ".Layer_Name" at -1006.87,-4296.96 h60
M16 Courtyards Bottom:
  text ".Layer_Name" at -1006.87,-4296.96 h60
Drill Drawing:
  circle w10: c4996.47,6763.13 r37.4
  circle w10: c4996.47,5248.3 r22.44
  circle w10: c4996.47,5248.3 r37.4
  lines w10: 4959.07,5042.58 4959.07,5061.28 4977.77,5079.98 4959.07,5098.68 4959.07,5117.38 4977.77,5117.38 4996.47,5098.68 5015.17,5117.38 5033.87,5117.38 5033.87,5098.68 5015.17,5079.98 5033.87,5061.28 5033.87,5042.58 5015.17,5042.58 4996.47,5061.28 4977.77,5042.58 4959.07,5042.58 ; 4959.07,5379.21 5033.87,5379.21 5033.87,5454.01 4959.07,5454.01 4959.07,5379.21 ; 4959.07,5566.22 4977.77,5566.22 4977.77,5547.52 5015.17,5547.52 5015.17,5566.22 5033.87,5566.22 5033.87,5603.63 5015.17,5603.63 5015.17,5622.33 4977.77,5622.33 4977.77,5603.63 4959.07,5603.63 4959.07,5566.22 ; 4959.07,5734.54 4977.77,5734.54 4996.47,5715.84 5015.17,5734.54 5033.87,5734.54 5015.17,5753.24 5033.87,5771.94 5015.17,5771.94 4996.47,5790.64 4977.77,5771.94 4959.07,5771.94 4977.77,5753.24 4959.07,5734.54 ; 4959.07,5902.85 4977.77,5902.85 4977.77,5884.15 5015.17,5884.15 5015.17,5902.85 5033.87,5902.85 5033.87,5940.26 5015.17,5940.26 5015.17,5958.96 4977.77,5958.96 4977.77,5940.26 4959.07,5940.26 4959.07,5902.85 ; 4959.07,6052.47 4996.47,6071.17 5033.87,6052.47 5015.17,6089.87 5033.87,6127.27 4996.47,6108.57 4959.07,6127.27 4977.77,6089.87 4959.07,6052.47 ; 4959.07,6295.59 5033.87,6295.59 4996.47,6220.78 4959.07,6295.59 ; 4959.07,6407.8 4977.77,6407.8 4996.47,6389.1 5015.17,6407.8 5033.87,6407.8 5015.17,6426.5 5033.87,6445.2 5015.17,6445.2 4996.47,6463.9 4977.77,6445.2 4959.07,6445.2 4977.77,6426.5 4959.07,6407.8 ; 4959.07,6632.22 5033.87,6632.22 4996.47,6557.41 4959.07,6632.22 ; 4959.07,6894.04 5033.87,6894.04 5033.87,6968.85 4959.07,6968.85 4959.07,6894.04 ; 4974.03,5742.02 4985.25,5742.02 4996.47,5730.8 5007.69,5742.02 5018.91,5742.02 5007.69,5753.24 5018.91,5764.46 5007.69,5764.46 4996.47,5775.68 4985.25,5764.46 4974.03,5764.46 4985.25,5753.24 4974.03,5742.02 ; 4974.03,5910.33 4985.25,5910.33 4985.25,5899.11 5007.69,5899.11 5007.69,5910.33 5018.91,5910.33 5018.91,5932.78 5007.69,5932.78 5007.69,5944 4985.25,5944 4985.25,5932.78 4974.03,5932.78 4974.03,5910.33 ; 4974.03,6617.26 5018.91,6617.26 4996.47,6572.37 4974.03,6617.26 ; 4974.03,6909 5018.91,6909 5018.91,6953.88 4974.03,6953.88 4974.03,6909
  lines w12: 4892.36,4992.08 14521.6,4992.08 ; 4892.36,7011.86 14521.6,7011.86 ; 5506.59,4823.77 5506.59,7180.17 ; 6244.53,4823.77 6244.53,7180.17 ; 7750.52,4823.77 7750.52,7180.17 ; 8314.26,4823.77 8314.26,7180.17 ; 9133.75,4823.77 9133.75,7180.17 ; 10354.04,4823.77 10354.04,7180.17 ; 11873.49,4823.77 11873.49,7180.17 ; 13553.69,4823.77 13553.69,7180.17 ; 4892.36,4823.77 14521.6,4823.77 14521.6,7180.17 4892.36,7180.17 4892.36,4823.77
  text "DRILL TABLE:" at 4885.33,7280.58 h80
  text "Symbol" at 4993.34,7062.35 h80.79
  text "Quantity" at 5557.08,7062.35 h80.79
  text "Finished Hole Size" at 6295.02,7062.35 h80.79
  text "Plated" at 7801.01,7062.35 h80.79
  text "Hole Type" at 8364.75,7062.35 h80.79
  text "Hole Length" at 9184.24,7062.35 h80.79
  text "Routed Path Length" at 10404.53,7062.35 h80.79
  text "Drill Layer Pair" at 11923.98,7062.35 h80.79
  text "Tolerannce" at 13604.18,7062.35 h80.79
  text "135" at 5557.08,6894.04 h67.33
  text "8.00mil (0.203mm)" at 6295.02,6894.04 h67.33
  text "PTH" at 7801.01,6894.04 h67.33
  text "Round" at 8364.75,6894.04 h67.33
  text "-" at 9184.24,6894.04 h67.33
  text "-" at 10404.53,6894.04 h67.33
  text "Top Layer - Bottom Layer" at 11923.98,6894.04 h67.33
  text "+3mil / -3mil" at 13604.18,6894.04 h67.33
  text "592" at 5557.08,6725.72 h67.33
  text "10.00mil (0.254mm)" at 6295.02,6725.72 h67.33
  text "PTH" at 7801.01,6725.72 h67.33
  text "Round" at 8364.75,6725.72 h67.33
  text "-" at 9184.24,6725.72 h67.33
  text "-" at 10404.53,6725.72 h67.33
  text "Top Layer - Bottom Layer" at 11923.98,6725.72 h67.33
  text "+3mil / -3mil" at 13604.18,6725.72 h67.33
  text "2618" at 5557.08,6557.41 h67.33
  text "12.00mil (0.305mm)" at 6295.02,6557.41 h67.33
  text "PTH" at 7801.01,6557.41 h67.33
  text "Round" at 8364.75,6557.41 h67.33
  text "-" at 9184.24,6557.41 h67.33
  text "-" at 10404.53,6557.41 h67.33
  text "Top Layer - Bottom Layer" at 11923.98,6557.41 h67.33
  text "+3mil / -3mil" at 13604.18,6557.41 h67.33
  text "125" at 5557.08,6389.1 h67.33
  text "12.10mil (0.307mm)" at 6295.02,6389.1 h67.33
  text "PTH" at 7801.01,6389.1 h67.33
  text "Round" at 8364.75,6389.1 h67.33
  text "-" at 9184.24,6389.1 h67.33
  text "-" at 10404.53,6389.1 h67.33
  text "Top Layer - Bottom Layer" at 11923.98,6389.1 h67.33
  text "+3mil / -3mil" at 13604.18,6389.1 h67.33
  text "10" at 5557.08,6220.78 h67.33
  text "33.47mil (0.850mm)" at 6295.02,6220.78 h67.33
  text "PTH" at 7801.01,6220.78 h67.33
  text "Round" at 8364.75,6220.78 h67.33
  text "-" at 9184.24,6220.78 h67.33
  text "-" at 10404.53,6220.78 h67.33
  text "Top Layer - Bottom Layer" at 11923.98,6220.78 h67.33
  text "+3mil / -3mil" at 13604.18,6220.78 h67.33
  text "15" at 5557.08,6052.47 h67.33
  text "40.00mil (1.016mm)" at 6295.02,6052.47 h67.33
  text "PTH" at 7801.01,6052.47 h67.33
  text "Round" at 8364.75,6052.47 h67.33
  text "-" at 9184.24,6052.47 h67.33
  text "-" at 10404.53,6052.47 h67.33
  text "Top Layer - Bottom Layer" at 11923.98,6052.47 h67.33
  text "+3mil / -3mil" at 13604.18,6052.47 h67.33
  text "28" at 5557.08,5884.15 h67.33
  text "40.16mil (1.020mm)" at 6295.02,5884.15 h67.33
  text "PTH" at 7801.01,5884.15 h67.33
  text "Round" at 8364.75,5884.15 h67.33
  text "-" at 9184.24,5884.15 h67.33
  text "-" at 10404.53,5884.15 h67.33
  text "Top Layer - Bottom Layer" at 11923.98,5884.15 h67.33
  text "+3mil / -3mil" at 13604.18,5884.15 h67.33
  text "8" at 5557.08,5715.84 h67.33
  text "42.00mil (1.067mm)" at 6295.02,5715.84 h67.33
  text "PTH" at 7801.01,5715.84 h67.33
  text "Round" at 8364.75,5715.84 h67.33
  text "-" at 9184.24,5715.84 h67.33
  text "-" at 10404.53,5715.84 h67.33
  text "Top Layer - Bottom Layer" at 11923.98,5715.84 h67.33
  text "+4mil / -0mil" at 13604.18,5715.84 h67.33
  text "8" at 5557.08,5547.52 h67.33
  text "51.18mil (1.300mm)" at 6295.02,5547.52 h67.33
  text "PTH" at 7801.01,5547.52 h67.33
  text "Round" at 8364.75,5547.52 h67.33
  text "-" at 9184.24,5547.52 h67.33
  text "-" at 10404.53,5547.52 h67.33
  text "Top Layer - Bottom Layer" at 11923.98,5547.52 h67.33
  text "+3mil / -3mil" at 13604.18,5547.52 h67.33
  text "32" at 5557.08,5379.21 h67.33
  text "63.00mil (1.600mm)" at 6295.02,5379.21 h67.33
  text "PTH" at 7801.01,5379.21 h67.33
  text "Round" at 8364.75,5379.21 h67.33
  text "-" at 9184.24,5379.21 h67.33
  text "-" at 10404.53,5379.21 h67.33
  text "Top Layer - Bottom Layer" at 11923.98,5379.21 h67.33
  text "+3mil / -3mil" at 13604.18,5379.21 h67.33
  text "10" at 5557.08,5210.89 h67.33
  text "125.98mil (3.200mm)" at 6295.02,5210.89 h67.33
  text "NPTH" at 7801.01,5210.89 h67.33
  text "Round" at 8364.75,5210.89 h67.33
  text "-" at 9184.24,5210.89 h67.33
  text "-" at 10404.53,5210.89 h67.33
  text "Top Layer - Bottom Layer" at 11923.98,5210.89 h67.33
  text "+2mil / -2mil" at 13604.18,5210.89 h67.33
  text "18" at 5557.08,5042.58 h67.33
  text "425.00mil (10.795mm)" at 6295.02,5042.58 h67.33
  text "PTH" at 7801.01,5042.58 h67.33
  text "Slot" at 8364.75,5042.58 h67.33
  text "73.00mil (1.854mm)" at 9184.24,5042.58 h67.33
  text "-352.00mil (-8.941mm)" at 10404.53,5042.58 h67.33
  text "Top Layer - Bottom Layer" at 11923.98,5042.58 h67.33
  text "+3mil / -3mil" at 13604.18,5042.58 h67.33
  text "3599 Total" at 5557.08,4874.26 h67.33
  text "Slot definitions :" at 4993.34,4714.03 h67.33
  text "Routed Path Length" at 6148.71,4714.03 h67.33
  text "= Calculated from tool start centre position to tool end centre position." at 7382.59,4714.03 h67.33
  text "Hole Length" at 6148.71,4604.29 h67.33
  text "= Routed Path Length + Tool Size = Slot length as defined in the PCB layout" at 6922.68,4604.29 h67.33
  text ".Layer_Name" at -1006.87,-4296.96 h60
M17 Embedded Cavity:
  text ".Layer_Name" at -1006.87,-4296.96 h60
M18 Embedded Assembly:
  text ".Layer_Name" at -1006.87,-4296.96 h60
M19 Embedded Keepout:
  text ".Layer_Name" at -1006.87,-4296.96 h60
Un-wanted:
  text "305-PD-22-0344" at 1575.71,4306.47 h40
  text "JUL 2022" at 1563.71,4186.92 h40
M21-Assembly_note:
  lines w6: 586.16,2037.5 612.16,2063.5 ; 612.16,1851.5 612.16,2063.5 ; 614.01,1556.23 614.01,1746.5 ; 638.16,2037.5 612.16,2063.5 ; 1438.03,2037.5 1464.03,2063.5 ; 1464.03,1851.5 1464.03,2063.5 ; 1465.88,1556.23 1465.88,1746.5 ; 1490.03,2037.5 1464.03,2063.5 ; 2289.89,2037.5 2315.89,2063.5 ; 2315.89,1851.5 2315.89,2063.5 ; 2317.75,1556.23 2317.75,1746.5 ; 2341.89,2037.5 2315.89,2063.5 ; 3141.76,2037.5 3167.76,2063.5 ; 3167.76,1851.5 3167.76,2063.5 ; 3169.61,1556.23 3169.61,1746.5 ; 3193.76,2037.5 3167.76,2063.5 ; 558.74,1451.23 558.74,1556.23 665.58,1556.23 665.58,1451.23 558.74,1451.23 ; 558.74,1746.5 558.74,1851.5 665.58,1851.5 665.58,1746.5 558.74,1746.5 ; 1410.6,1451.23 1410.6,1556.23 1517.45,1556.23 1517.45,1451.23 1410.6,1451.23 ; 1410.6,1746.5 1410.6,1851.5 1517.45,1851.5 1517.45,1746.5 1410.6,1746.5 ; 2262.47,1451.23 2262.47,1556.23 2369.32,1556.23 2369.32,1451.23 2262.47,1451.23 ; 2262.47,1746.5 2262.47,1851.5 2369.32,1851.5 2369.32,1746.5 2262.47,1746.5 ; 3114.34,1451.23 3114.34,1556.23 3221.18,1556.23 3221.18,1451.23 3114.34,1451.23 ; 3114.34,1746.5 3114.34,1851.5 3221.18,1851.5 3221.18,1746.5 3114.34,1746.5
  text "RECEPTACLE : 0300-2-15-01-47-01-10-0" at 935.08,7992.91 h60
  text "RECEPTACLE" at 439.71,2076.6 h35
  text "RECEPTACLE" at 1291.58,2076.6 h35
  text "RECEPTACLE" at 2143.45,2076.6 h35
  text "RECEPTACLE" at 2995.31,2076.6 h35

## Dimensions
0,7750 to 3780,7750 on M2 Board Dimensions
0,7750 to 0,0 on M2 Board Dimensions
-83.87,-2731.1 to 916.13,-2731.1 on M2 Board Dimensions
